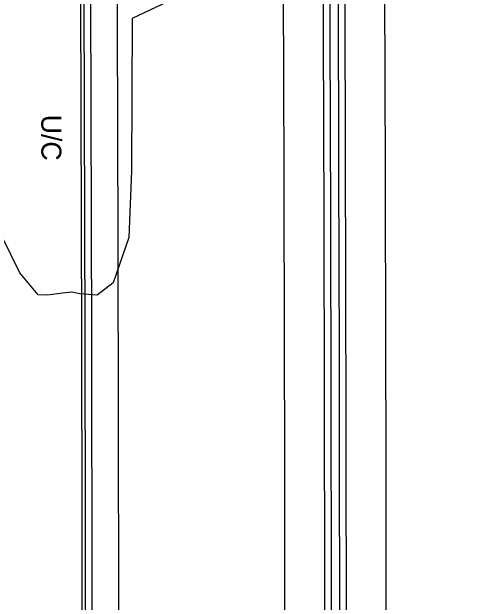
# Model space of a CAD drawing. Extents: x 588843 to 2552415, y 180129 to 269402.
# Drawn here: x 593923.8 to 594066, y 188094.1 to 188272 of the extents above; entities that cross this region are included whole.
import ezdxf

# ---------------------------------------------------------------- set-up
doc = ezdxf.new("R2010")
doc.units = 0
for name, color, linetype in [('E_AREA', 7, 'Continuous'), ('E_AREA_Text', 7, 'Continuous'), ('P_RDWY_BarrierConc', 7, 'Continuous'), ('P_RDWY_C_and_G', 7, 'Continuous'), ('P_RDWY_C_and_GBack', 7, 'Continuous'), ('P_RDWY_C_and_GFace', 7, 'Continuous'), ('P_RDWY_PavtEdge', 7, 'Continuous')]:
    doc.layers.add(name, color=color, linetype=linetype)

# ---------------------------------------------------------------- blocks, each defined once
blk = doc.blocks.new('UCA_6')
at = {"layer": 'E_AREA_Text'}
blk.add_text('U/C', height=12, dxfattribs=at).set_placement((-15.33, -6))

msp = doc.modelspace()

# ---------------------------------------------------------------- linework, layer by layer
at = {"layer": 'E_AREA'}
msp.add_lwpolyline([(594080.03, 188326.7), (593960.02, 188269.93), (593959.79, 188224.09), (593958.99, 188204.02), (593954.26, 188190.34), (593954.26, 188190.34), (593949.51, 188186.59), (593944.26, 188187), (593941.85, 188187.56), (593939.04, 188187.18), (593934.5, 188186.63), (593931.77, 188186.75), (593926.19, 188193.37), (593920.78, 188204.36), (593917.55, 188208.92), (593907.24, 188213.57), (593904.4, 188218.18), (593901.59, 188228.84), (593901.34, 188235.8), (593902.36, 188240.42), (593902.44, 188246.16), (593902.46, 188249.15), (593902.79, 188250.54), (593900.56, 188306.25)], dxfattribs=at)
at = {"layer": 'P_RDWY_BarrierConc'}
for radius in [57298.53, 57300.53, 57303.03, 57305.03]:
    msp.add_arc((536719.48, 188049.55), radius, 359.769059, 0.6479963, dxfattribs=at)
at = {"layer": 'P_RDWY_C_and_G'}
msp.add_arc((536719.48, 188049.55), 57228.53, 359.920406, 0.647996, dxfattribs=at)
at = {"layer": 'P_RDWY_C_and_GBack'}
msp.add_arc((536719.48, 188049.55), 57225.53, 359.920487, 0.647996, dxfattribs=at)
at = {"layer": 'P_RDWY_C_and_GFace'}
msp.add_arc((536719.48, 188049.55), 57226.53, 359.920487, 0.647996, dxfattribs=at)
at = {"layer": 'P_RDWY_PavtEdge'}
for radius, start, end in [(57236.53, 359.944955, 0.647996), (57286.53, 359.769059, 0.647996), (57317.03, 359.769059, 0.6479963)]:
    msp.add_arc((536719.48, 188049.55), radius, start, end, dxfattribs=at)

# ---------------------------------------------------------------- block references
at = {"layer": 'E_AREA_Text', "xscale": 0.4999999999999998, "yscale": 0.49999999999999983, "rotation": -89.80573595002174}
msp.add_blockref('UCA_6', (593935.69, 188233.3), dxfattribs=at)

doc.saveas('drawing.dxf')
